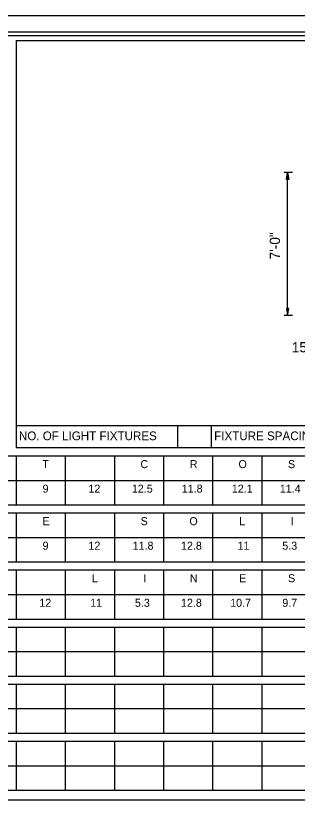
# Model space of a CAD drawing. Extents: x 121688 to 126625, y -22764 to -19972.
# Drawn here: x 125352.7 to 125518.3, y -22217.9 to -21754.2 of the extents above; entities that cross this region are included whole.
import ezdxf

# ---------------------------------------------------------------- set-up
doc = ezdxf.new("R2010")
doc.units = 0
for name, color, linetype in [('GSDims', 7, 'Continuous'), ('GSSign', 7, 'Continuous'), ('PlotBorder_dp', 7, 'Continuous'), ('SheetBorder_dp', 7, 'Continuous'), ('SheetLinesMisc2_dp', 7, 'Continuous'), ('TextMinor', 7, 'Continuous')]:
    doc.layers.add(name, color=color, linetype=linetype)

msp = doc.modelspace()

# ---------------------------------------------------------------- linework, layer by layer
at = {"layer": 'GSDims'}
for p, q in [((125515.61, -21846.48), (125510.61, -21846.48)), ((125512.61, -21930.48), (125512.61, -21846.48)), ((125515.61, -21846.48), (125515.61, -21846.48)), ((125515.61, -21930.48), (125510.61, -21930.48)), ((125515.61, -21930.48), (125515.61, -21930.48))]:
    msp.add_line(p, q, dxfattribs=at)
for points in [[(125512.61, -21846.48), (125513.28, -21850.48), (125511.94, -21850.48)], [(125512.61, -21930.48), (125513.28, -21926.48), (125511.94, -21926.48)]]:
    msp.add_lwpolyline(points, close=True, dxfattribs=at)
at = {"layer": 'PlotBorder_dp'}
msp.add_lwpolyline([(125072.61, -22751.63), (126625.18, -22751.63), (126625.18, -21754.22), (125072.61, -21754.22)], close=True, dxfattribs=at)
at = {"layer": 'SheetBorder_dp'}
msp.add_line((125124.37, -21763.63), (126573.42, -21763.63), dxfattribs=at)
at = {"layer": 'SheetLinesMisc2_dp'}
for p, q in [((125126.93, -21765.86), (126571.13, -21765.86)), ((125352.94, -21768.85), (125844.12, -21768.85)), ((125352.94, -21768.85), (125352.94, -22008.11)), ((125352.94, -21995.29), (125844.12, -21995.29)), ((125447.81, -21995.29), (125447.81, -22008.11)), ((125467.69, -21995.29), (125467.69, -22008.11)), ((125352.94, -22008.11), (125844.12, -22008.11)), ((125133.86, -22013.04), (125844.12, -22013.04)), ((125352.94, -22013.04), (125352.94, -22041.9)), ((125381.83, -22013.04), (125381.83, -22041.9)), ((125410.72, -22013.04), (125410.72, -22041.9)), ((125439.61, -22013.04), (125439.61, -22041.9)), ((125468.51, -22013.04), (125468.51, -22041.9)), ((125497.4, -22013.04), (125497.4, -22041.9)), ((125133.86, -22027.46), (125844.12, -22027.46)), ((125133.86, -22041.9), (125844.12, -22041.9)), ((125133.86, -22046.6), (125844.12, -22046.6)), ((125352.94, -22046.6), (125352.94, -22075.45)), ((125381.83, -22046.6), (125381.83, -22075.45)), ((125410.72, -22046.6), (125410.72, -22075.45)), ((125439.61, -22046.6), (125439.61, -22075.45)), ((125468.51, -22046.6), (125468.51, -22075.45)), ((125497.4, -22046.6), (125497.4, -22075.45)), ((125133.86, -22061.03), (125844.12, -22061.02)), ((125133.86, -22075.45), (125844.12, -22075.45)), ((125133.86, -22080.16), (125844.12, -22080.16)), ((125352.94, -22080.16), (125352.94, -22109.01)), ((125381.83, -22080.16), (125381.83, -22109.01)), ((125410.72, -22080.16), (125410.72, -22109.01)), ((125439.61, -22080.16), (125439.61, -22109.01)), ((125468.51, -22080.16), (125468.51, -22109.01)), ((125497.4, -22080.16), (125497.4, -22109.01)), ((125133.86, -22094.59), (125844.12, -22094.59)), ((125133.86, -22109.01), (125844.12, -22109.01)), ((125133.86, -22113.72), (125844.12, -22113.72)), ((125352.94, -22113.72), (125352.94, -22142.58)), ((125381.83, -22113.72), (125381.83, -22142.58)), ((125410.72, -22113.72), (125410.72, -22142.58)), ((125439.61, -22113.72), (125439.61, -22142.58)), ((125468.51, -22113.72), (125468.51, -22142.58)), ((125497.4, -22113.72), (125497.4, -22142.58)), ((125133.86, -22128.15), (125844.12, -22128.15)), ((125133.86, -22142.58), (125844.12, -22142.58)), ((125133.86, -22147.28), (125844.12, -22147.28)), ((125352.94, -22147.28), (125352.94, -22176.14)), ((125381.83, -22147.28), (125381.83, -22176.14)), ((125410.72, -22147.28), (125410.72, -22176.14)), ((125439.61, -22147.28), (125439.61, -22176.14)), ((125468.51, -22147.28), (125468.51, -22176.14)), ((125497.4, -22147.28), (125497.4, -22176.14)), ((125133.86, -22161.71), (125844.12, -22161.71)), ((125133.86, -22176.14), (125844.12, -22176.14)), ((125133.86, -22180.84), (125844.12, -22180.84)), ((125352.94, -22180.84), (125352.94, -22209.69)), ((125381.83, -22180.84), (125381.83, -22209.69)), ((125410.72, -22180.84), (125410.72, -22209.69)), ((125439.61, -22180.84), (125439.61, -22209.69)), ((125468.51, -22180.84), (125468.51, -22209.69)), ((125497.4, -22180.84), (125497.4, -22209.69)), ((125133.86, -22195.26), (125844.12, -22195.26)), ((125133.86, -22209.69), (125844.12, -22209.69)), ((125126.93, -22215.36), (126571.13, -22215.36))]:
    msp.add_line(p, q, dxfattribs=at)

# ---------------------------------------------------------------- texts
at = {"layer": 'GSDims'}
msp.add_text('7\'-0"', height=6, rotation=90, dxfattribs=at).set_placement((125508.14, -21897.51))
msp.add_text('15.55"', height=6, dxfattribs=at).set_placement((125515.1, -21952.14))
at = {"layer": 'GSSign'}
for s, height, p in [('T', 4.71, (125368.39, -22020.25)), ('C', 4.71, (125426.08, -22020.25)), ('R', 4.71, (125455.09, -22020.25)), ('O', 4.71, (125483.77, -22020.25)), ('S', 4.71, (125512.89, -22020.25)), ('9', 4.71, (125368.5, -22034.68)), ('12', 4.705, (125395.5, -22034.68)), ('12.5', 4.705, (125421.04, -22034.68)), ('11.8', 4.705, (125450.39, -22034.68)), ('12.1', 4.705, (125479.84, -22034.68)), ('11.4', 4.705, (125508.07, -22034.68)), ('E', 4.71, (125368.5, -22053.81)), ('S', 4.71, (125426.19, -22053.81)), ('O', 4.71, (125454.87, -22053.81)), ('L', 4.71, (125484.21, -22053.81)), ('I', 4.71, (125514.46, -22053.81)), ('9', 4.71, (125368.5, -22068.24)), ('12', 4.705, (125395.5, -22068.24)), ('11.8', 4.705, (125421.49, -22068.24)), ('12.8', 4.705, (125449.94, -22068.24)), ('11', 4.705, (125483.21, -22068.24)), ('5.3', 4.705, (125509.53, -22068.24)), ('L', 4.71, (125397.52, -22087.38)), ('I', 4.71, (125427.76, -22087.38)), ('N', 4.71, (125455.09, -22087.38)), ('E', 4.71, (125484.1, -22087.38)), ('S', 4.71, (125512.89, -22087.38)), ('12', 4.705, (125366.6, -22101.81)), ('11', 4.705, (125396.51, -22101.81)), ('5.3', 4.705, (125422.83, -22101.81)), ('12.8', 4.705, (125449.94, -22101.81)), ('10.7', 4.705, (125478.84, -22101.81)), ('9.7', 4.705, (125509.53, -22101.81))]:
    msp.add_text(s, height=height, dxfattribs=at).set_placement(p)
at = {"layer": 'TextMinor'}
for s, p in [('NO. OF LIGHT FIXTURES', (125354.59, -22003.82)), ('FIXTURE SPACING', (125469.46, -22003.82))]:
    msp.add_text(s, height=5.102, dxfattribs=at).set_placement(p)

doc.saveas('drawing.dxf')
